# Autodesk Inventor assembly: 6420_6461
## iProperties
Author: Ole Germer
Shininess: 64.0
Angle Display Precision: 2
Document Length Units: 11272
Document Angle Units: 11286
Document Time Units: 11279
Document Mass Units: 11290
Document Length Units Precision: 3
Document Angle Units Precision: 2
Compacted: True
PropertySet Name: _Private Model Information
Created: 2002-10
Part Number: 6420_6461
Document SubType Name: Assembly
Designer: Ole Germer
Control State: 0
Master: False
Checked Out: False
PropertySet Name: Design Tracking Control
Density: 0.0
Volumn: 0.0
Area: 0.0
PropertySet Name: Model Information
